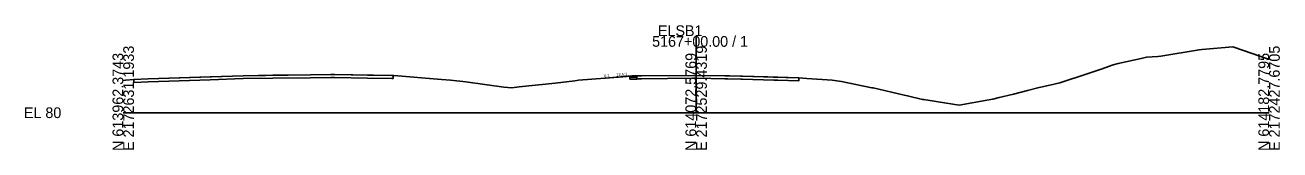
# Model space of a CAD drawing. Extents: x -26 to 1303, y -3010 to 12023.
# Drawn here: x -25.7 to 302.8, y -2509.7 to -2477.2 of the extents above; entities that cross this region are included whole.
import ezdxf

# ---------------------------------------------------------------- set-up
doc = ezdxf.new("R2010")
doc.units = 0
for name, color, linetype in [('RD_GPK_XS_Cell', 7, 'Continuous'), ('RD_XS_Base', 7, 'Continuous'), ('RD_XS_ExGround', 7, 'Continuous'), ('RD_XS_ExPaveRet', 7, 'Continuous'), ('RD_XS_Greenside', 7, 'Continuous'), ('RD_XS_Pave', 7, 'Continuous'), ('RD_XS_PaveOvlay_CP', 7, 'Continuous'), ('RD_XS_TieSlope', 7, 'Continuous'), ('RD_XS_TX_ShdSlope', 7, 'Continuous'), ('RD_XS_TX_Slope', 7, 'Continuous')]:
    doc.layers.add(name, color=color, linetype=linetype)

msp = doc.modelspace()

# ---------------------------------------------------------------- linework, layer by layer
at = {"layer": 'RD_GPK_XS_Cell'}
for p, q in [((150, -2500), (150, -2480)), ((0, -2500), (150, -2500)), ((150, -2500), (300, -2500))]:
    msp.add_line(p, q, dxfattribs=at)
at = {"layer": 'RD_XS_Base'}
for p, q in [((132.63, -2490.72), (133.13, -2490.71)), ((132.63, -2491.22), (132.63, -2490.72)), ((132.63, -2490.8), (132.63, -2490.8)), ((133.13, -2491.21), (132.63, -2491.22)), ((133.1, -2491.21), (133.1, -2491.21)), ((133.13, -2490.71), (134.49, -2490.71)), ((134.49, -2491.21), (133.13, -2491.21))]:
    msp.add_line(p, q, dxfattribs=at)
at = {"layer": 'RD_XS_ExGround'}
msp.add_lwpolyline([(0, -2491.58), (0.6, -2491.52), (2.75, -2491.33), (6.57, -2491.2), (31.41, -2490.34), (49.02, -2490.11), (54.7, -2490.04), (65.55, -2490.22), (70.64, -2490.31), (70.89, -2490.3), (83.36, -2491.3), (85.72, -2491.5), (89.66, -2491.97), (99.66, -2493.34), (101.73, -2493.49), (103.68, -2493.25), (113.13, -2492.26), (118.21, -2491.66), (119.2, -2491.5), (130.78, -2490.66), (133.56, -2490.42), (134.49, -2490.39), (135.66, -2490.38), (149.74, -2490.26), (158.76, -2490.42), (161.66, -2490.47), (168.73, -2490.68), (173.49, -2490.82), (176.92, -2490.92), (179.01, -2491.06), (185.62, -2491.5), (188.02, -2491.84), (196.02, -2493.48), (196.09, -2493.49), (196.1, -2493.5), (196.11, -2493.5), (196.32, -2493.55), (204.48, -2495.41), (205.3, -2495.59), (209.24, -2496.53), (209.61, -2496.59), (213.41, -2497.2), (218.85, -2498.06), (218.85, -2498.06), (226.6, -2496.67), (227.64, -2496.45), (229.38, -2496.05), (233.06, -2495.15), (236.77, -2494.22), (239.42, -2493.5), (243.78, -2492.53), (244.08, -2492.46), (245.22, -2492.17), (252.34, -2489.9), (253.42, -2489.48), (256.06, -2488.66), (259.19, -2487.48), (260.51, -2487.15), (266.54, -2485.83), (267.58, -2485.59), (267.92, -2485.5), (270.84, -2485.32), (271.7, -2485.23), (281.7, -2483.56), (282.37, -2483.51), (290.52, -2482.84), (295.87, -2484.66), (300, -2486.09)], dxfattribs=at)
at = {"layer": 'RD_XS_ExPaveRet'}
for p, q in [((64.04, -2490.2), (63.94, -2490.2)), ((150.2, -2490.27), (149.74, -2490.26)), ((134.49, -2491.14), (134.49, -2491.21)), ((170.19, -2490.72), (168.73, -2490.68))]:
    msp.add_line(p, q, dxfattribs=at)
for points in [[(70.64, -2490.31), (70.64, -2490.31), (70.64, -2490.64), (70.64, -2491.06), (70.64, -2491.06), (70.33, -2491.05), (63.94, -2490.95), (55.3, -2490.8), (54.7, -2490.79), (54.39, -2490.79), (49.02, -2490.86), (39.21, -2490.99), (31.41, -2491.09), (22.72, -2491.39), (6.57, -2491.95), (2.75, -2492.08), (2.75, -2492.08), (2.75, -2492.08), (2.75, -2492.08), (2.75, -2491.66), (2.75, -2491.33), (2.75, -2491.33), (2.75, -2491.33), (2.75, -2491.33), (6.57, -2491.2), (22.72, -2490.64), (31.41, -2490.34), (39.21, -2490.24), (49.02, -2490.11), (54.39, -2490.04), (54.7, -2490.04), (55.3, -2490.05), (63.94, -2490.2), (70.33, -2490.3), (70.64, -2490.31)], [(2.75, -2491.33), (2.75, -2491.66), (2.75, -2492.08), (2.75, -2492.08), (2.75, -2492.08), (6.57, -2491.95), (22.72, -2491.39), (31.41, -2491.09), (39.21, -2490.99), (49.02, -2490.86), (54.39, -2490.79), (54.7, -2490.79), (55.3, -2490.8), (63.94, -2490.95), (70.33, -2491.05), (70.64, -2491.06), (70.64, -2490.64), (70.64, -2490.31), (70.33, -2490.3), (64.04, -2490.2)], [(54.39, -2490.04), (49.02, -2490.11), (39.21, -2490.24), (31.41, -2490.34)], [(63.94, -2490.2), (55.3, -2490.05), (54.7, -2490.04), (54.39, -2490.04)], [(176.92, -2490.92), (171.4, -2490.76), (170.31, -2490.73), (162.12, -2490.48), (161.66, -2490.47), (158.3, -2490.41), (157.55, -2490.4), (150.2, -2490.27), (149.74, -2490.26), (149.35, -2490.26), (135.66, -2490.38), (134.52, -2490.39), (134.49, -2490.39), (134.49, -2490.39), (134.49, -2490.47), (134.49, -2491.14), (134.49, -2491.14), (134.52, -2491.14), (135.66, -2491.13), (149.35, -2491.01), (149.74, -2491.01), (150.2, -2491.02), (157.55, -2491.15), (158.3, -2491.16), (161.66, -2491.22), (162.12, -2491.23), (170.31, -2491.48), (171.4, -2491.51), (176.92, -2491.67), (176.92, -2491.67), (176.92, -2491.67), (176.92, -2491.59), (176.92, -2490.92), (176.92, -2490.92), (176.92, -2490.92)], [(149.74, -2490.26), (149.35, -2490.26), (135.66, -2490.38), (134.52, -2490.39), (134.49, -2490.39), (134.49, -2490.39)], [(157.59, -2490.4), (157.55, -2490.4), (150.2, -2490.27)], [(31.41, -2490.34), (22.72, -2490.64), (6.57, -2491.2), (6.57, -2491.2), (2.75, -2491.33), (2.75, -2491.33), (2.75, -2491.33)], [(134.49, -2490.39), (134.49, -2490.47), (134.49, -2491.14), (134.49, -2491.14), (134.52, -2491.14), (135.66, -2491.13), (149.35, -2491.01), (149.74, -2491.01), (150.2, -2491.02), (157.55, -2491.15), (158.3, -2491.16), (161.66, -2491.22), (162.12, -2491.23), (170.31, -2491.48), (171.4, -2491.51), (176.92, -2491.67), (176.92, -2491.67), (176.92, -2491.59), (176.92, -2490.92), (176.92, -2490.92), (171.4, -2490.76), (170.31, -2490.73), (170.19, -2490.72)], [(158.74, -2490.42), (158.3, -2490.41), (157.59, -2490.4)], [(168.73, -2490.68), (161.66, -2490.47), (158.76, -2490.42), (158.74, -2490.42)]]:
    msp.add_lwpolyline(points, dxfattribs=at)
at = {"layer": 'RD_XS_Greenside'}
msp.add_line((127.13, -2490.88), (126.64, -2490.96), dxfattribs=at)
at = {"layer": 'RD_XS_Pave'}
for p, q in [((134.49, -2490.39), (133.13, -2490.4)), ((133.13, -2490.4), (133.13, -2490.56)), ((133.13, -2490.46), (133.13, -2490.46)), ((133.13, -2490.56), (134.49, -2490.55)), ((133.13, -2490.56), (133.13, -2490.71)), ((133.13, -2490.62), (133.13, -2490.62)), ((133.13, -2490.62), (133.13, -2490.62)), ((133.13, -2490.62), (133.13, -2490.62))]:
    msp.add_line(p, q, dxfattribs=at)
at = {"layer": 'RD_XS_PaveOvlay_CP'}
msp.add_line((133.13, -2490.46), (133.13, -2490.46), dxfattribs=at)
at = {"layer": 'RD_XS_TieSlope'}
msp.add_line((133.13, -2490.4), (127.13, -2490.88), dxfattribs=at)

# ---------------------------------------------------------------- texts
at = {"layer": 'RD_GPK_XS_Cell'}
for s, p in [('5167+00.00 / 1', (138.48, -2482.8)), ('ELSB1', (140, -2480)), ('EL 80', (-26, -2501.4))]:
    msp.add_text(s, height=2.8, dxfattribs=at).set_placement(p)
for s, p in [('E 2172631.1933', (2.8, -2510)), ('E 2172529.4319', (152.8, -2510)), ('E 2172427.6705', (302.8, -2510)), ('N 613962.3743', (0, -2510)), ('N 614072.5769', (150, -2510)), ('N 614182.7795', (300, -2510))]:
    msp.add_text(s, height=2.8, rotation=90, dxfattribs=at).set_placement(p)
at = {"layer": 'RD_XS_TX_ShdSlope'}
msp.add_text('12.5:1', height=0.75, rotation=4.5739, dxfattribs=at).set_placement((129.13, -2490.5))
at = {"layer": 'RD_XS_TX_Slope'}
msp.add_text('6:1', height=0.75, rotation=9.4642, dxfattribs=at).set_placement((125.92, -2490.81))

doc.saveas('drawing.dxf')
